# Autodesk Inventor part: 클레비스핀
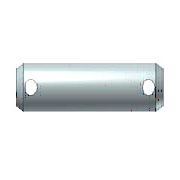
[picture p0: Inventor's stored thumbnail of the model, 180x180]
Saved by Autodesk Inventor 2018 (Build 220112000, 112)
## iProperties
IsCustomPart: 1
Created: 2012-02
Part Number: 클레비스핀
Material: 강철
Description: 머리가 없는 클레비스 핀 B
Document SubType Name: Modeling
Standard: ISO 2340
Designer: mduedu
Standard Revision: Second edition 1986-11-01
Standards Organization: ISO
Language: ko-KR
Size Designation: B - 8 x 45
Categories: <MemberInstance><Categories><Category DisplayName="조임쇠" InternalName="e4da775c-781d-43d5-af7c-5136215cf5a6" Mnemonic="FSTN"><Category DisplayName="핀" InternalNa
Density: 7.85 g/cm^3
Appearance: 반광택
Author: mduedu
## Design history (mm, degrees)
sketch "스케치1"
  geometry: L1 (-4.5, 0)-(-4.5, 4); L2 (-4.5, 4)-(35.5, 4); L3 (35.5, 4)-(35.5, 0); L4 (-4.5, 0)-(35.5, 0); L5 (0, -2)-(0, 5) reference; L6 (-13.5, 0)-(49.5, 0) reference; C1 r 1 at (-1, 0); C2 r 1 at (32, 0)
  constraints: 8 end point, 2 centre point, 2 perpendicular, 2 point on line, 1 collinear, 1 parallel, 1 tangent, 1 vertical
  dimensions: "d0" = 8 diameter of L2 L4 (= NND); "d1" = 40 distance of L1.end L2.end (= NLG); "d2" = 3.5 distance from line of L1 C1.centre (= DIST1); "d3" = 3.5 distance from line of L3 C2.centre (= DIST2); "d4" = 2 diameter of C1 (= BOR1); "d5" = 2 diameter of C2 (= BOR2)
revolve "본체" stored, may be unused: angle "d7" = 90 deg
extrude "구멍1" cut sketch "스케치1" extent not by distance; taper "d6" = 0 deg; stored distance "d8" = 10
extrude "구멍2" cut sketch "스케치1" extent not by distance; taper "d13" = 0 deg; stored distance "d14" = 10
workaxis "Work Axis1"
workaxis "Work Axis2"
workplane "Work Plane1"
node "작업 평면5"
node "작업 평면6"
body "Solid1"
chamfer "모따기2" distance "d9" = 2 (= PHH2); stored, may be unused: angle "d10" = 30 deg (= FAWI2), second distance "d40" = 2 (= PHH2)
chamfer "모따기1" distance "d11" = 2 (= PHH1); stored, may be unused: angle "d12" = 30 deg (= FAWI1), second distance "d41" = 2 (= PHH1)
other parameters: "NLG" = 40 [user parameter; used in 1 equation term], "NND" = 8 [user parameter; used in 1 equation term], "PHH1" = 2 [user parameter; used in 3 equation terms], "PHH2" = 2 (= PHH1) [user parameter; used in 2 equation terms], "FAWI1" = 30 deg [user parameter; used in 1 equation term], "FAWI2" = 30 deg [user parameter; used in 1 equation term], "DIST1" = 3.5 [user parameter; used in 4 equation terms], "DIST2" = 3.5 (= DIST1) [user parameter; used in 1 equation term], "BOR1" = 2 [user parameter; used in 4 equation terms], "BOR2" = 2 (= BOR1) [user parameter; used in 1 equation term], "d15" = 0, "d42" = 0, "d43" = 0, "d44" = -4.5 (= -0.5 x BOR1 - DIST1), "d45" = -4.5 (= -0.5 x BOR1 - DIST1), "d47" = 0, "d48" = 0, "d49" = 0, "d50" = 0, "d51" = 0, "d52" = 0
